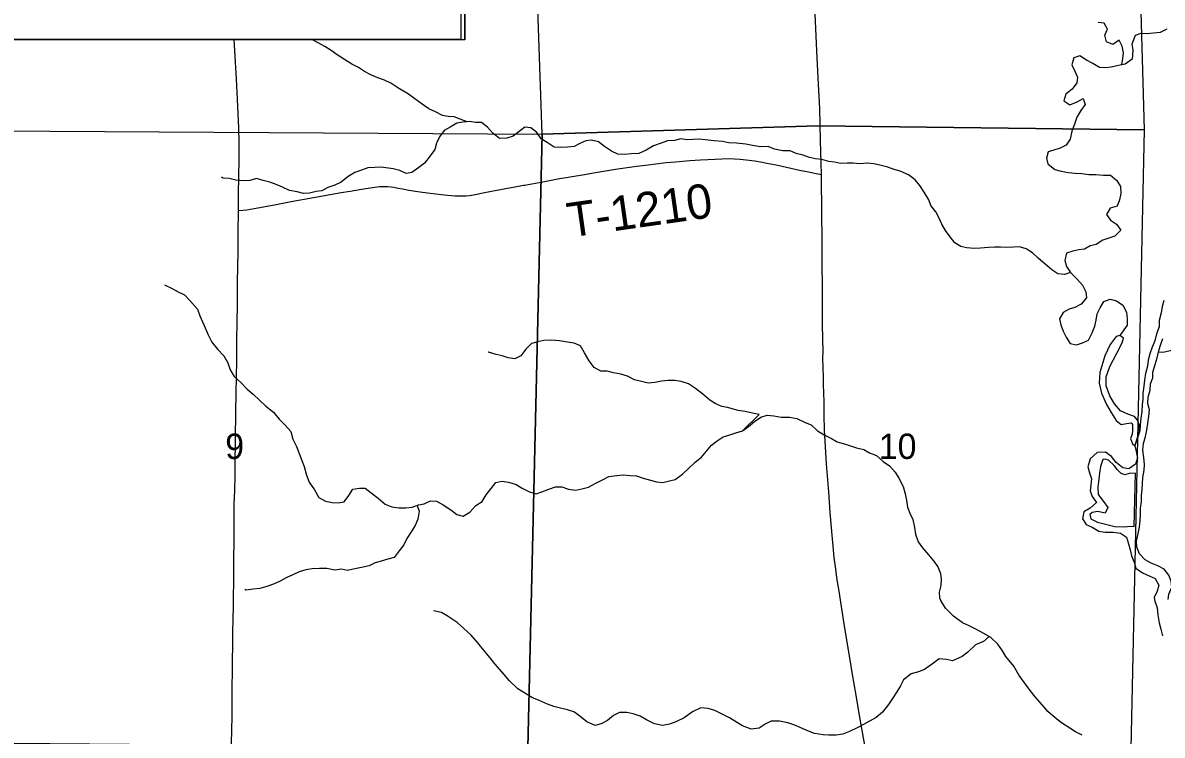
# Model space of a CAD drawing. Extents: x 0 to 34, y 0 to 22.
# Drawn here: x 5.352 to 7.232, y 14.853 to 16.027 of the extents above; entities that cross this region are included whole.
import ezdxf

# ---------------------------------------------------------------- set-up
doc = ezdxf.new("R2010")
doc.units = 0
for name, color, linetype in [('Default', 7, 'Continuous'), ('GM_X_County_Road', 7, 'Continuous'), ('GM_X_Major_River', 7, 'Continuous'), ('GM_X_Minor_River', 7, 'Continuous'), ('GM_X_Section', 7, 'Continuous'), ('GM_X_Section_Text', 7, 'Continuous'), ('GM_X_Township_Road', 7, 'Continuous'), ('GM_X_Township_Road_Text', 7, 'Continuous'), ('SH_Text', 7, 'Continuous')]:
    doc.layers.add(name, color=color, linetype=linetype)

msp = doc.modelspace()

# ---------------------------------------------------------------- linework, layer by layer
at = {"layer": 'Default'}
for points in [[(4.1282, 16.747), (6.0753, 16.747), (6.0753, 16), (6.0818, 16), (6.0818, 16.7475), (4.1282, 16.7475)], [(4.1282, 16.747), (6.0818, 16.747), (6.0818, 15.9995), (4.1282, 15.9995)]]:
    msp.add_lwpolyline(points, close=True, dxfattribs=at)
at = {"layer": 'GM_X_County_Road'}
for points in [[(6.6699, 15.777), (6.6687, 15.8332), (6.6672, 15.886), (6.6652, 15.9264), (6.6632, 15.9698), (6.6589, 16.0536), (6.6574, 16.0877), (6.6562, 16.1156), (6.6525, 16.1932), (6.6504, 16.2429), (6.6481, 16.2925), (6.6469, 16.3205), (6.6458, 16.3461)], [(5.7081, 15.7178), (5.7083, 15.7303), (5.7083, 15.7489), (5.7087, 15.7706), (5.7092, 15.8048), (5.7093, 15.8296), (5.7087, 15.8544), (5.7066, 15.9007), (5.7051, 15.9351), (5.702, 15.9815), (5.7011, 16)], [(6.7414, 14.8361), (6.7355, 14.8697), (6.7324, 14.8881), (6.7272, 14.9187), (6.7245, 14.934), (6.7213, 14.9524), (6.7168, 14.98), (6.7094, 15.026), (6.7052, 15.0504), (6.7018, 15.0718), (6.699, 15.0902), (6.6962, 15.1086), (6.693, 15.1301), (6.6912, 15.1455), (6.6884, 15.1764), (6.6845, 15.2198), (6.682, 15.2537), (6.6784, 15.3002), (6.6762, 15.3375), (6.675, 15.3557), (6.6746, 15.3807), (6.6743, 15.4025), (6.6736, 15.4307), (6.6733, 15.4428), (6.6729, 15.4582), (6.6725, 15.4737), (6.6726, 15.4861), (6.6726, 15.4923), (6.6725, 15.4986), (6.6724, 15.5016), (6.6721, 15.5136), (6.672, 15.5226), (6.6718, 15.5474), (6.6717, 15.5878), (6.6711, 15.6344), (6.671, 15.6623), (6.6706, 15.7214), (6.6702, 15.7649), (6.6699, 15.777)], [(5.6969, 14.8365), (5.6974, 14.8629), (5.6976, 14.8815), (5.6978, 14.9032), (5.6979, 14.9187), (5.6982, 14.9711), (5.6987, 15.0049), (5.6991, 15.0235), (5.6995, 15.0421), (5.6998, 15.0669), (5.7, 15.0823), (5.7003, 15.104), (5.7005, 15.1225), (5.7007, 15.1442), (5.7011, 15.1721), (5.7013, 15.1907), (5.7011, 15.2123), (5.7013, 15.2341), (5.7019, 15.2558), (5.7025, 15.2807), (5.7025, 15.293), (5.7027, 15.3084), (5.7027, 15.3144), (5.703, 15.3235), (5.7033, 15.339), (5.7035, 15.3575), (5.7036, 15.3696), (5.7036, 15.3808), (5.7036, 15.3883), (5.7036, 15.3965), (5.7041, 15.4056), (5.7046, 15.4242), (5.7049, 15.4366), (5.7053, 15.477), (5.7057, 15.5049), (5.706, 15.5327), (5.7064, 15.5634), (5.7066, 15.5912), (5.7067, 15.6005), (5.7074, 15.6499), (5.7078, 15.69), (5.708, 15.7095), (5.7081, 15.7178)]]:
    msp.add_lwpolyline(points, dxfattribs=at)
at = {"layer": 'GM_X_Major_River'}
for points in [[(7.2351, 15.5695), (7.232, 15.5593), (7.2304, 15.5491), (7.2273, 15.5366), (7.2272, 15.5259), (7.2226, 15.5146), (7.2202, 15.5032), (7.2159, 15.4923), (7.212, 15.4817), (7.2089, 15.4711), (7.2081, 15.4609), (7.2046, 15.4491), (7.2033, 15.4378), (7.2017, 15.4279), (7.2005, 15.4162), (7.2001, 15.4067), (7.1992, 15.3972), (7.1984, 15.3866), (7.1968, 15.3752), (7.1959, 15.3646), (7.1951, 15.3544), (7.1946, 15.3531)], [(7.1946, 15.3532), (7.194, 15.3642), (7.1914, 15.3722), (7.1866, 15.3784), (7.1756, 15.3819), (7.1635, 15.3873), (7.1538, 15.3992), (7.1456, 15.4121), (7.14, 15.4289), (7.1398, 15.4437), (7.1456, 15.4607), (7.1572, 15.4826), (7.166, 15.4996), (7.1683, 15.5075), (7.1623, 15.5118), (7.1563, 15.5103), (7.1463, 15.4968), (7.1378, 15.4782), (7.1292, 15.4506), (7.1283, 15.4332), (7.132, 15.4168), (7.1402, 15.3978), (7.148, 15.3848), (7.1562, 15.3714), (7.1645, 15.3649), (7.1732, 15.3667), (7.1808, 15.3678), (7.183, 15.3647), (7.1833, 15.3552), (7.1825, 15.3488), (7.1798, 15.342), (7.1831, 15.3332), (7.1869, 15.3298)], [(7.214, 15.1364), (7.2042, 15.1418), (7.1949, 15.1517), (7.1904, 15.1624), (7.1897, 15.1723), (7.1925, 15.1852), (7.1948, 15.1954), (7.1961, 15.2064), (7.1962, 15.2162), (7.1966, 15.2269), (7.1982, 15.2378), (7.1983, 15.2481), (7.1992, 15.2576), (7.1996, 15.267), (7.2001, 15.2773), (7.2025, 15.2894), (7.2029, 15.2989), (7.2019, 15.3107), (7.2001, 15.3228), (7.2013, 15.3338), (7.2045, 15.3452), (7.2068, 15.3554), (7.2084, 15.3664), (7.21, 15.3789), (7.2113, 15.3891), (7.2083, 15.3998), (7.2092, 15.41), (7.2123, 15.4214), (7.2128, 15.432), (7.2166, 15.4418), (7.2167, 15.4513), (7.2206, 15.4638), (7.2241, 15.4751), (7.2261, 15.485), (7.2296, 15.4959), (7.2335, 15.5069)], [(7.1869, 15.3298), (7.1946, 15.3532)], [(7.1946, 15.3531), (7.1869, 15.3298)], [(7.1869, 15.3298), (7.1895, 15.3203), (7.1913, 15.3092), (7.1882, 15.2994), (7.1771, 15.2916), (7.1673, 15.2935), (7.1564, 15.3024), (7.1485, 15.3123), (7.1387, 15.3192), (7.1251, 15.3186), (7.1136, 15.3085), (7.1094, 15.2952), (7.1123, 15.285), (7.1156, 15.2751), (7.1144, 15.2656), (7.1132, 15.2557), (7.1169, 15.2462), (7.124, 15.2363), (7.1133, 15.2269), (7.1031, 15.2209), (7.1007, 15.2096), (7.1067, 15.2), (7.1168, 15.1954), (7.1278, 15.1892), (7.138, 15.1876), (7.1516, 15.1875), (7.1633, 15.1858), (7.1735, 15.1793), (7.1764, 15.1679), (7.1794, 15.158), (7.1816, 15.1485), (7.186, 15.1378), (7.1886, 15.1279), (7.1999, 15.1202), (7.2105, 15.1152), (7.2206, 15.1109), (7.2266, 15.0998), (7.2239, 15.09), (7.2192, 15.0794), (7.2203, 15.0737)], [(7.188, 15.2846), (7.1778, 15.284), (7.1706, 15.2821), (7.1646, 15.2841), (7.1585, 15.2902), (7.1529, 15.2975), (7.1439, 15.3059), (7.1375, 15.3075), (7.1341, 15.3071), (7.1306, 15.2954), (7.1286, 15.2848), (7.127, 15.2704), (7.1261, 15.2617), (7.1268, 15.2495), (7.1354, 15.2377), (7.1425, 15.2278), (7.1379, 15.2187), (7.1262, 15.2215), (7.1167, 15.22), (7.1129, 15.2167), (7.1147, 15.2094), (7.1256, 15.204), (7.1385, 15.2005), (7.1543, 15.1969), (7.1702, 15.196), (7.1801, 15.197), (7.1858, 15.1966)], [(7.1858, 15.1966), (7.188, 15.2846)], [(7.242, 15.0762), (7.2431, 15.0852), (7.2482, 15.0966), (7.2471, 15.1065), (7.243, 15.1164), (7.2355, 15.1263), (7.225, 15.1317), (7.214, 15.1364)], [(7.2203, 15.0737), (7.2237, 15.0624), (7.225, 15.0511), (7.2273, 15.0378), (7.23, 15.0272), (7.2327, 15.0162)]]:
    msp.add_lwpolyline(points, dxfattribs=at)
at = {"layer": 'GM_X_Minor_River'}
for points in [[(7.1656, 15.9581), (7.1673, 15.9686), (7.1682, 15.9781), (7.1664, 15.9891), (7.1615, 15.9986), (7.1509, 15.9919), (7.1403, 15.9962), (7.1378, 16.0072), (7.142, 16.017), (7.1364, 16.0266), (7.1266, 16.0282)], [(6.0854, 15.8644), (6.0741, 15.8688), (6.0643, 15.8723), (6.0544, 15.8732), (6.0446, 15.8748), (6.0333, 15.8806), (6.022, 15.8853), (6.0114, 15.8933), (5.9994, 15.9022), (5.9885, 15.9099), (5.9711, 15.9203), (5.9598, 15.928), (5.9489, 15.933), (5.9383, 15.9369), (5.9266, 15.9416), (5.9161, 15.947), (5.9063, 15.9539), (5.895, 15.959), (5.8829, 15.9671), (5.8709, 15.9744), (5.8611, 15.9817), (5.8505, 15.9883), (5.8396, 15.9944), (5.8291, 16)], [(7.2397, 16.0172), (7.2287, 16.0116), (7.2177, 16.0106), (7.2071, 16.0092), (7.1972, 16.0097), (7.1874, 16.0063), (7.1823, 15.9923), (7.1837, 15.9825), (7.1825, 15.9677), (7.171, 15.9594), (7.1604, 15.9569), (7.1483, 15.9544), (7.1388, 15.9533), (7.129, 15.9538), (7.1177, 15.9603), (7.1071, 15.9661), (7.0962, 15.9731), (7.0863, 15.9698), (7.0832, 15.958), (7.088, 15.9477), (7.0925, 15.9378), (7.0913, 15.9283), (7.0836, 15.9178), (7.0733, 15.9096), (7.0702, 15.899), (7.08, 15.892), (7.0921, 15.8972), (7.1017, 15.9024), (7.1054, 15.8929), (7.0981, 15.8827), (7.0912, 15.8718), (7.0873, 15.8601), (7.0834, 15.8487), (7.0803, 15.8355), (7.0737, 15.8257), (7.0638, 15.8205), (7.0536, 15.8175), (7.0441, 15.8146), (7.0414, 15.8044), (7.0436, 15.7949), (7.0552, 15.7853), (7.0654, 15.7829), (7.0775, 15.7805), (7.0889, 15.7792), (7.0998, 15.7788), (7.1112, 15.7775), (7.1229, 15.7774), (7.1354, 15.7761), (7.1468, 15.776), (7.1573, 15.7672), (7.1637, 15.7573), (7.1639, 15.7459), (7.162, 15.7353), (7.1577, 15.7251), (7.1463, 15.7218), (7.1402, 15.7112), (7.1469, 15.7017), (7.1567, 15.6951), (7.1642, 15.6852), (7.1539, 15.6758), (7.1444, 15.6721), (7.1345, 15.6691), (7.1231, 15.662), (7.1136, 15.6595), (7.1041, 15.6543), (7.0946, 15.6532), (7.0847, 15.651), (7.0745, 15.6477), (7.0717, 15.6352), (7.0743, 15.6253), (7.0807, 15.6158), (7.0916, 15.6051), (7.1006, 15.5947), (7.1061, 15.584)], [(7.0807, 15.6158), (7.0708, 15.6125), (7.0602, 15.6137), (7.05, 15.6199), (7.0384, 15.6302), (7.0278, 15.6394), (7.0181, 15.6483), (7.0079, 15.6544), (6.9966, 15.658), (6.9867, 15.6573), (6.9754, 15.657), (6.9655, 15.6575), (6.9557, 15.6576), (6.9458, 15.6569), (6.9326, 15.6556), (6.922, 15.6553), (6.9099, 15.6562), (6.9, 15.6585), (6.8899, 15.6647), (6.8824, 15.6746), (6.8745, 15.685), (6.8689, 15.6953), (6.8641, 15.7055), (6.8589, 15.7158), (6.8506, 15.7262), (6.8473, 15.7357), (6.8394, 15.7479), (6.8323, 15.759), (6.8249, 15.7685), (6.8139, 15.7766), (6.8, 15.7828), (6.7898, 15.7856), (6.7796, 15.7895), (6.7686, 15.7922), (6.7565, 15.795), (6.7459, 15.7959), (6.7334, 15.7949), (6.7221, 15.7957), (6.7122, 15.7958), (6.7016, 15.7955), (6.6918, 15.7975), (6.682, 15.7988), (6.6706, 15.8019), (6.6601, 15.8032), (6.6502, 15.8052), (6.6397, 15.809), (6.6283, 15.8118), (6.6185, 15.8161), (6.6064, 15.8162), (6.5924, 15.819), (6.5822, 15.8233), (6.5693, 15.823), (6.5565, 15.825), (6.5452, 15.8274), (6.53, 15.8291), (6.5175, 15.8296), (6.5066, 15.8316), (6.4933, 15.8329), (6.4782, 15.8345), (6.468, 15.8358), (6.4581, 15.8351), (6.4479, 15.8344), (6.4381, 15.8361), (6.4274, 15.8331), (6.4161, 15.8329), (6.4058, 15.8292), (6.3929, 15.8244), (6.3811, 15.8176), (6.3686, 15.8117), (6.3561, 15.8111), (6.3458, 15.8104), (6.3341, 15.8109), (6.3235, 15.8159), (6.3122, 15.8236), (6.3021, 15.8309), (6.2907, 15.8337), (6.2813, 15.8327), (6.2714, 15.8286), (6.2619, 15.8237), (6.2509, 15.8223), (6.2395, 15.8217), (6.2289, 15.8225), (6.2176, 15.8299), (6.2075, 15.836), (6.2004, 15.8463), (6.1906, 15.854), (6.1804, 15.8553), (6.1613, 15.8403), (6.1507, 15.8373), (6.1386, 15.8367), (6.1276, 15.8455), (6.119, 15.8555), (6.1089, 15.8628), (6.099, 15.8629), (6.0892, 15.8649), (6.0786, 15.8635), (6.0687, 15.862), (6.0577, 15.8553), (6.0478, 15.8497), (6.0397, 15.8392), (6.0351, 15.829)], [(6.0351, 15.829), (6.032, 15.8184), (6.0247, 15.8082), (6.0151, 15.7962), (6.0056, 15.789), (5.9942, 15.7808), (5.9847, 15.779), (5.9745, 15.7837), (5.9632, 15.7868), (5.9435, 15.7893), (5.9333, 15.789), (5.9215, 15.788), (5.9113, 15.7843), (5.8999, 15.7806), (5.8889, 15.7739), (5.8774, 15.7645), (5.8672, 15.7597), (5.8554, 15.7556), (5.8459, 15.7504), (5.8364, 15.749), (5.8254, 15.7464), (5.8155, 15.7457), (5.805, 15.7485), (5.7925, 15.7509), (5.7808, 15.7563), (5.7702, 15.7606), (5.76, 15.7645), (5.7487, 15.7673), (5.7377, 15.7704), (5.7271, 15.7671), (5.7169, 15.7668), (5.704, 15.7681), (5.6927, 15.7705), (5.6821, 15.7713), (5.6802, 15.7729)], [(5.5863, 15.5951), (5.5976, 15.59), (5.6089, 15.5835), (5.6191, 15.5788), (5.6281, 15.5692), (5.6405, 15.5551), (5.6446, 15.544), (5.6486, 15.5345), (5.6531, 15.5246), (5.6579, 15.5128), (5.6643, 15.5006), (5.6733, 15.4891), (5.6838, 15.4784), (5.6905, 15.4665), (5.6942, 15.4551), (5.7009, 15.4441), (5.7118, 15.4341), (5.7223, 15.4234), (5.7325, 15.4149), (5.7426, 15.4049), (5.7531, 15.395), (5.7659, 15.3854), (5.7753, 15.3735), (5.7854, 15.3639), (5.7948, 15.3536), (5.7981, 15.341), (5.8041, 15.3288), (5.8081, 15.317), (5.8129, 15.3056), (5.8166, 15.2957), (5.8203, 15.2812), (5.8248, 15.2698), (5.8337, 15.2572), (5.8408, 15.2446), (5.8518, 15.2384), (5.8627, 15.2361), (5.8726, 15.236), (5.8824, 15.2374), (5.8905, 15.2476), (5.897, 15.2581), (5.9076, 15.2599), (5.9174, 15.2598), (5.9272, 15.2525), (5.9385, 15.2433), (5.9502, 15.2337), (5.9611, 15.2294), (5.9725, 15.2274), (5.9842, 15.2277), (5.9948, 15.2287), (6.0051, 15.2324), (6.0145, 15.2342), (6.0252, 15.239), (6.035, 15.2386), (6.046, 15.2324), (6.0584, 15.2243), (6.0682, 15.2166), (6.0787, 15.2138), (6.0898, 15.2202), (6.0997, 15.2315), (6.1104, 15.2382), (6.1169, 15.2491), (6.1249, 15.2593), (6.133, 15.2691), (6.1425, 15.2717), (6.1538, 15.27), (6.1663, 15.2661), (6.1764, 15.2599), (6.1885, 15.2541), (6.1991, 15.2506), (6.2086, 15.2539), (6.2204, 15.2584), (6.2314, 15.2624), (6.2416, 15.262), (6.2525, 15.2581), (6.2646, 15.2568), (6.2749, 15.2586), (6.2859, 15.2615), (6.2969, 15.2675), (6.3087, 15.2735), (6.319, 15.2794), (6.3322, 15.2808), (6.3429, 15.2822), (6.3542, 15.2806), (6.3648, 15.2801), (6.3758, 15.2766), (6.3882, 15.2734), (6.398, 15.2703), (6.4086, 15.2694), (6.4193, 15.272), (6.4287, 15.2742), (6.4406, 15.2832), (6.4501, 15.2918), (6.4616, 15.3027), (6.4722, 15.3109), (6.4806, 15.3207), (6.4887, 15.3309), (6.4982, 15.338), (6.5081, 15.3447), (6.5191, 15.3481), (6.529, 15.351), (6.5396, 15.3547)], [(7.1061, 15.584), (7.1072, 15.5738), (7.0984, 15.5632), (7.0881, 15.558), (7.0786, 15.5551), (7.0687, 15.5499), (7.0626, 15.5393), (7.0652, 15.5294), (7.0689, 15.5188), (7.0737, 15.5092), (7.0804, 15.4985), (7.091, 15.4962), (7.1005, 15.4995), (7.1104, 15.5039), (7.1165, 15.5164), (7.1212, 15.527), (7.1232, 15.5368), (7.1251, 15.5474), (7.1298, 15.5576), (7.1359, 15.5678), (7.1465, 15.5715), (7.1571, 15.5687), (7.1673, 15.5618), (7.1733, 15.55), (7.1747, 15.539), (7.1742, 15.5287), (7.1623, 15.5118)], [(7.226, 15.4845), (7.2363, 15.4849), (7.2477, 15.4874), (7.2583, 15.4892), (7.269, 15.4948), (7.2796, 15.4981), (7.2895, 15.5045), (7.299, 15.5104), (7.3108, 15.5156), (7.3218, 15.5171), (7.3339, 15.5177), (7.3434, 15.5199), (7.3551, 15.5205), (7.3665, 15.5223), (7.3798, 15.5222), (7.3911, 15.5243), (7.4025, 15.5227), (7.4138, 15.5226), (7.4237, 15.5206), (7.4377, 15.5187)], [(6.5396, 15.3547), (6.5671, 15.3817), (6.5565, 15.3837), (6.5444, 15.3865), (6.5327, 15.3878), (6.5153, 15.3932), (6.5055, 15.3949), (6.4957, 15.3991), (6.4859, 15.4053), (6.4746, 15.4149), (6.4622, 15.4241), (6.4509, 15.4318), (6.4388, 15.4357), (6.4279, 15.4377), (6.4169, 15.4375), (6.4059, 15.4364), (6.3953, 15.4343), (6.3843, 15.4332), (6.3729, 15.4356), (6.3616, 15.4388), (6.3499, 15.4446), (6.339, 15.4481), (6.3272, 15.4501), (6.3167, 15.4529), (6.3061, 15.453), (6.2948, 15.4588), (6.2869, 15.4702), (6.2791, 15.4832), (6.2727, 15.4946), (6.2618, 15.4993), (6.2508, 15.5005), (6.2376, 15.503), (6.2247, 15.5042), (6.2118, 15.5036), (6.202, 15.5014), (6.1917, 15.4985), (6.1822, 15.4891), (6.1741, 15.4782), (6.1639, 15.4733), (6.1533, 15.4749), (6.1431, 15.4781), (6.1333, 15.4804), (6.1208, 15.4844), (6.12, 15.4844)], [(6.5396, 15.3547), (6.5499, 15.3614), (6.5598, 15.3697), (6.5701, 15.3772), (6.5807, 15.3805), (6.5917, 15.3792), (6.6038, 15.3772), (6.6174, 15.3771), (6.6292, 15.3747), (6.6431, 15.3685), (6.6533, 15.3646), (6.6634, 15.3546), (6.6744, 15.3477), (6.6864, 15.3419), (6.6962, 15.3365), (6.7061, 15.3337), (6.7162, 15.3302), (6.7276, 15.3267), (6.7397, 15.3239), (6.7495, 15.3181), (6.7608, 15.3138), (6.7717, 15.3039), (6.7822, 15.2969), (6.7916, 15.2862), (6.7976, 15.2767), (6.805, 15.2625), (6.8083, 15.2507), (6.8105, 15.2401), (6.8119, 15.2287), (6.816, 15.2188), (6.8209, 15.2085), (6.8234, 15.1948), (6.8252, 15.1842), (6.8296, 15.1716), (6.8367, 15.1613), (6.8469, 15.1502), (6.8547, 15.1403), (6.8618, 15.1303), (6.8667, 15.1193), (6.8673, 15.1098), (6.8669, 15.0995), (6.8641, 15.0882), (6.8647, 15.0787), (6.8672, 15.0747)], [(6.003, 15.2316), (6.0065, 15.2218), (6.0041, 15.2089), (5.9995, 15.1983), (5.9933, 15.1877), (5.986, 15.1768), (5.981, 15.1666), (5.9734, 15.1564), (5.9649, 15.1455), (5.9547, 15.143), (5.9437, 15.1396), (5.9338, 15.1367), (5.9236, 15.1319), (5.911, 15.1293), (5.9, 15.1268), (5.8883, 15.1243), (5.8781, 15.1262), (5.8671, 15.1245), (5.8538, 15.1272), (5.8421, 15.1277), (5.8296, 15.1271), (5.8194, 15.1253), (5.8084, 15.122), (5.7981, 15.1172), (5.7867, 15.1123), (5.7772, 15.1067), (5.7661, 15.1015), (5.7548, 15.0975), (5.7434, 15.0945), (5.7328, 15.0935), (5.7202, 15.0917), (5.7187, 15.0929)], [(7.1004, 14.8523), (7.0893, 14.8583), (7.0798, 14.864), (7.0662, 14.8727), (7.0555, 14.881), (7.0434, 14.8916), (7.0346, 14.9022), (7.0224, 14.9158), (7.0144, 14.926), (7.0068, 14.9366), (6.9961, 14.951), (6.9874, 14.9665), (6.9744, 14.9821), (6.9687, 14.9919), (6.9611, 15.0029), (6.9493, 15.0139), (6.9368, 15.021), (6.9257, 15.0271), (6.9128, 15.0335), (6.903, 15.0376), (6.8877, 15.049), (6.8748, 15.0622), (6.8672, 15.0747)], [(6.9465, 15.0155), (6.9376, 15.007), (6.9243, 15.0013), (6.9118, 14.9895), (6.902, 14.9822), (6.8864, 14.975), (6.8762, 14.9772), (6.8641, 14.9783), (6.8535, 14.9703), (6.8402, 14.9608), (6.83, 14.957), (6.8178, 14.9535), (6.8054, 14.944), (6.8005, 14.9337), (6.7944, 14.9242), (6.7872, 14.9128), (6.7804, 14.9029), (6.771, 14.8904), (6.7604, 14.8816), (6.7392, 14.8702), (6.729, 14.8648), (6.7165, 14.8587), (6.7051, 14.8541), (6.6945, 14.8526), (6.6823, 14.8525), (6.6729, 14.8529), (6.6588, 14.8555), (6.6459, 14.8604), (6.6349, 14.8653), (6.6243, 14.8698), (6.6144, 14.8728), (6.6011, 14.8758), (6.5871, 14.8758), (6.5772, 14.8708), (6.5674, 14.8643), (6.5541, 14.8624), (6.54, 14.8677), (6.5298, 14.8741), (6.5184, 14.8813), (6.5074, 14.8869), (6.4941, 14.8933), (6.4834, 14.8967), (6.4713, 14.8978), (6.4573, 14.8913), (6.4437, 14.8814), (6.43, 14.8745), (6.4194, 14.8707), (6.4077, 14.8684), (6.3944, 14.871), (6.3815, 14.8778), (6.3708, 14.8838), (6.3594, 14.888), (6.3488, 14.8902), (6.337, 14.8898), (6.3272, 14.8852), (6.3173, 14.8768), (6.3067, 14.8711), (6.2969, 14.8684), (6.2832, 14.8748), (6.2714, 14.8839), (6.2615, 14.8911), (6.2509, 14.8945), (6.2395, 14.8971), (6.2285, 14.9001), (6.2179, 14.9035), (6.2031, 14.9103), (6.1932, 14.9144), (6.1833, 14.9201), (6.1689, 14.9288), (6.1556, 14.942), (6.1434, 14.9564), (6.1312, 14.9704), (6.1236, 14.9802), (6.1148, 14.9904), (6.103, 15.0048), (6.092, 15.0177), (6.0794, 15.029), (6.0688, 15.0385), (6.0543, 15.0483), (6.0429, 15.0547), (6.03, 15.0577)]]:
    msp.add_lwpolyline(points, dxfattribs=at)
at = {"layer": 'GM_X_Section'}
for points in [[(5.2115, 16), (5.2159, 15.85), (6.2093, 15.844), (6.1739, 16.8615), (6.1193, 16.8628), (5.1862, 16.8638), (5.1896, 16.747), (6.0753, 16.747), (6.0753, 16)], [(7.1741, 16.8653), (7.2023, 15.8508), (6.6641, 15.8573), (6.2093, 15.844), (6.1739, 16.8615), (7.1264, 16.8648)], [(5.2159, 15.85), (6.2093, 15.844), (6.1854, 14.8314), (5.1991, 14.84)], [(7.2023, 15.8508), (7.1806, 14.8307), (6.1854, 14.8314), (6.2093, 15.844), (6.6641, 15.8573)]]:
    msp.add_lwpolyline(points, close=True, dxfattribs=at)
at = {"layer": 'GM_X_Township_Road'}
for points in [[(6.1804, 15.7598), (6.1924, 15.762), (6.2105, 15.7652), (6.2353, 15.7699), (6.279, 15.7773), (6.2942, 15.7798), (6.3205, 15.7843), (6.3304, 15.7859), (6.3459, 15.7883), (6.3649, 15.7908), (6.38, 15.7927), (6.4137, 15.7968), (6.4291, 15.7984), (6.4527, 15.8005), (6.4704, 15.8015), (6.4946, 15.8027), (6.5059, 15.8031), (6.5178, 15.8035), (6.5268, 15.8032), (6.5362, 15.8025), (6.546, 15.8017), (6.56, 15.7999), (6.5696, 15.7983), (6.5802, 15.7962), (6.5981, 15.7926), (6.6339, 15.7846), (6.6485, 15.7814), (6.6613, 15.7788), (6.6699, 15.777)], [(5.7081, 15.7178), (5.7155, 15.7182), (5.722, 15.719), (5.7403, 15.7221), (5.7678, 15.7273), (5.7952, 15.7326), (5.8319, 15.7394), (5.8778, 15.7475), (5.8922, 15.7499), (5.9112, 15.7531), (5.933, 15.7566), (5.9406, 15.7573), (5.9473, 15.7577), (5.9545, 15.7575), (5.9603, 15.7568), (5.9645, 15.7562), (5.9715, 15.755), (5.9789, 15.7536), (5.9892, 15.7515), (6.0003, 15.7498), (6.0116, 15.7481), (6.0243, 15.7467), (6.0433, 15.7445), (6.053, 15.7433), (6.0597, 15.7427), (6.0652, 15.7423), (6.0722, 15.742), (6.0792, 15.7421), (6.0841, 15.7423), (6.0893, 15.7428), (6.099, 15.7445), (6.1112, 15.7468), (6.1259, 15.7497), (6.164, 15.7568), (6.1784, 15.7595), (6.1804, 15.7598)]]:
    msp.add_lwpolyline(points, dxfattribs=at)
at = {"layer": 'SH_Text'}
msp.add_lwpolyline([(4.1282, 16.747), (6.0753, 16.747), (6.0753, 15.9995), (4.1282, 15.9995)], close=True, dxfattribs=at)

# ---------------------------------------------------------------- texts
at = {"layer": 'GM_X_Section_Text'}
for s, height, p in [('9', 0.0419, (5.6863, 15.3081)), ('10', 0.04186, (6.7646, 15.3081))]:
    msp.add_text(s, height=height, rotation=0, dxfattribs=at).set_placement(p)
at = {"layer": 'GM_X_Township_Road_Text'}
msp.add_text('T-1210', height=0.05682, rotation=8.1059, dxfattribs=at).set_placement((6.2546, 15.6733))

doc.saveas('drawing.dxf')
